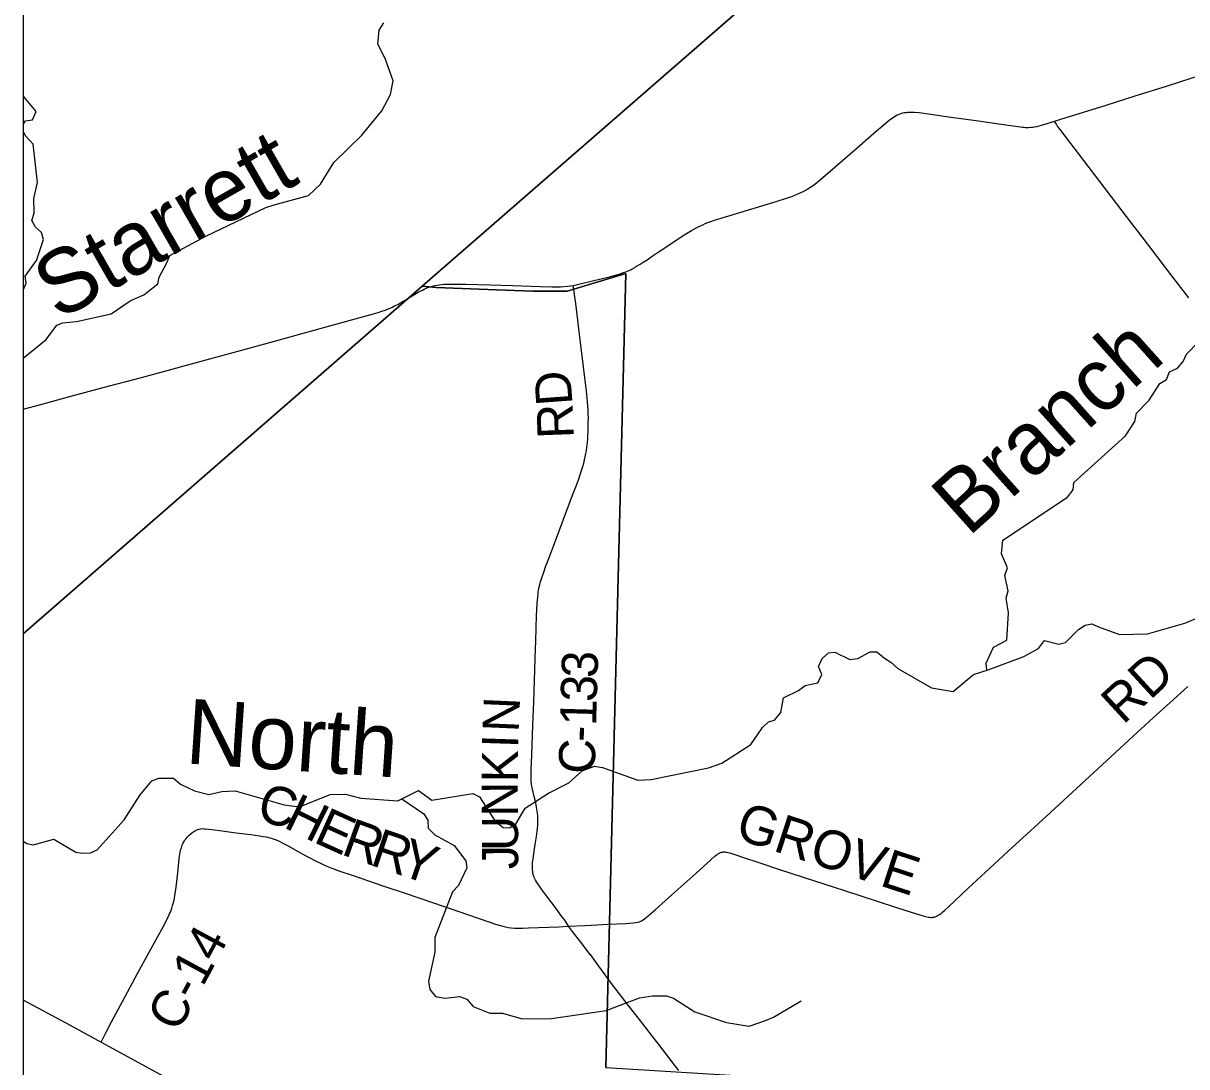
# Model space of a CAD drawing. Extents: x -13.9 to 69.1, y -25.2 to 26.1.
# Drawn here: x 1.757 to 3.383, y 18.903 to 20.361 of the extents above; entities that cross this region are included whole.
import ezdxf

# ---------------------------------------------------------------- set-up
doc = ezdxf.new("R2010")
doc.units = 0
for name, color, linetype in [('GM_X_County_Road', 7, 'Continuous'), ('GM_X_County_Road_Text', 7, 'Continuous'), ('GM_X_Minor_River', 7, 'Continuous'), ('GM_X_Minor_River_Text', 7, 'Continuous'), ('GM_X_Township', 7, 'Continuous'), ('GM_X_Township_Road', 7, 'Continuous'), ('SH_Data', 7, 'Continuous')]:
    doc.layers.add(name, color=color, linetype=linetype)

msp = doc.modelspace()

# ---------------------------------------------------------------- linework, layer by layer
at = {"layer": 'GM_X_County_Road'}
for points in [[(3.1987, 20.2246), (3.2075, 20.2273), (3.2707, 20.2469), (3.3115, 20.2598), (3.3566, 20.2741), (3.3911, 20.285), (3.4288, 20.2967), (3.4851, 20.3141), (3.5064, 20.3207), (3.5287, 20.3277), (3.5536, 20.3355), (3.5681, 20.3403), (3.5706, 20.3415), (3.5726, 20.3428), (3.577, 20.3461)], [(2.6062, 20.0171), (2.6084, 20.0182), (2.6104, 20.0194), (2.6121, 20.0205), (2.6194, 20.0248), (2.6237, 20.0275), (2.6293, 20.0311), (2.635, 20.0349), (2.6462, 20.0426), (2.6677, 20.057), (2.6796, 20.0647), (2.6911, 20.0717), (2.6994, 20.0763), (2.7027, 20.0779), (2.7069, 20.08), (2.7103, 20.0815), (2.7141, 20.083), (2.7184, 20.0845), (2.7235, 20.0863), (2.7389, 20.0911), (2.774, 20.1018), (2.8097, 20.1125), (2.824, 20.117), (2.8302, 20.1191), (2.8345, 20.1208), (2.8387, 20.1225), (2.8423, 20.124), (2.8463, 20.1259), (2.8499, 20.1278), (2.8535, 20.1298), (2.8567, 20.1319), (2.8603, 20.1344), (2.8637, 20.1368), (2.8717, 20.1433), (2.923, 20.1876), (2.9496, 20.2109), (2.9604, 20.2202), (2.9678, 20.2263), (2.9701, 20.228), (2.9724, 20.2295), (2.9744, 20.2309), (2.9766, 20.2321), (2.9789, 20.2333), (2.9806, 20.2341), (2.9828, 20.235), (2.985, 20.2357), (2.9868, 20.2361), (2.9889, 20.2366), (2.9911, 20.2369), (2.9932, 20.2372), (2.9954, 20.2373), (2.9976, 20.2374), (3.0003, 20.2374), (3.0031, 20.2373), (3.0096, 20.2367), (3.0321, 20.2334), (3.0474, 20.2313), (3.0924, 20.2251), (3.1206, 20.221), (3.1538, 20.2163), (3.1561, 20.2161), (3.1582, 20.216), (3.1622, 20.2159), (3.1655, 20.2162), (3.1683, 20.2164), (3.1709, 20.2167), (3.174, 20.2173), (3.177, 20.218), (3.1803, 20.219), (3.1884, 20.2213), (3.1987, 20.2246)], [(2.526, 19.9951), (2.5318, 19.9963), (2.5547, 20.0019), (2.573, 20.0063), (2.5816, 20.0085), (2.587, 20.01), (2.5927, 20.0118), (2.5963, 20.013), (2.5992, 20.0141), (2.6019, 20.0151), (2.605, 20.0165), (2.6062, 20.0171)], [(2.2928, 19.9756), (2.296, 19.9776), (2.309, 19.9855), (2.3121, 19.9872), (2.315, 19.9887), (2.3176, 19.99), (2.3201, 19.9911), (2.3227, 19.9922), (2.3259, 19.9933), (2.3293, 19.9943), (2.3324, 19.995), (2.3356, 19.9956), (2.3391, 19.9961), (2.3423, 19.9965), (2.345, 19.9967)], [(2.345, 19.9967), (2.3463, 19.9968), (2.3574, 19.997), (2.3756, 19.9968), (2.4093, 19.9959), (2.4414, 19.9951), (2.4795, 19.9938), (2.4961, 19.9933), (2.5021, 19.9933), (2.5079, 19.9933), (2.5128, 19.9936), (2.5175, 19.9939), (2.522, 19.9944), (2.526, 19.9951)], [(2.5195, 19.0996), (2.5164, 19.1043), (2.514, 19.1081), (2.5096, 19.1139), (2.502, 19.1243), (2.4886, 19.1424), (2.4817, 19.1517), (2.4786, 19.1559), (2.4773, 19.1578), (2.4747, 19.1617), (2.4733, 19.1641), (2.4723, 19.1661), (2.4714, 19.168), (2.4707, 19.1698), (2.47, 19.1721), (2.4695, 19.1742), (2.4692, 19.1763), (2.4689, 19.1787), (2.4688, 19.1811), (2.4688, 19.1835), (2.4688, 19.1858), (2.4691, 19.1881), (2.4698, 19.1939), (2.4719, 19.208), (2.4728, 19.2138), (2.4746, 19.225), (2.4756, 19.2324), (2.476, 19.2369), (2.4763, 19.2403), (2.4764, 19.2436), (2.4764, 19.2468), (2.4764, 19.2507), (2.4762, 19.254), (2.4759, 19.2575), (2.4756, 19.2605), (2.4752, 19.2635), (2.4747, 19.2663), (2.4741, 19.2695), (2.4735, 19.2721), (2.4714, 19.2808), (2.469, 19.2912), (2.4682, 19.2951), (2.4676, 19.2987), (2.4672, 19.3019), (2.467, 19.3047), (2.467, 19.3108), (2.4673, 19.3201), (2.4675, 19.3291), (2.4679, 19.3385), (2.4696, 19.3813), (2.4707, 19.4134), (2.4716, 19.4426), (2.4727, 19.4741), (2.4734, 19.4985), (2.4747, 19.5341), (2.4755, 19.5502), (2.4762, 19.5599), (2.4767, 19.5638), (2.477, 19.5667), (2.4775, 19.5693), (2.4779, 19.5717), (2.4784, 19.5739), (2.4791, 19.5766), (2.4798, 19.5795), (2.4807, 19.5824), (2.4825, 19.588), (2.4846, 19.5946), (2.4872, 19.6019), (2.4916, 19.6135), (2.5009, 19.6383), (2.5167, 19.6796), (2.5259, 19.7042), (2.5303, 19.716), (2.5336, 19.7248), (2.538, 19.7377), (2.5393, 19.742), (2.5406, 19.7468), (2.5417, 19.7513), (2.5426, 19.7554), (2.5435, 19.7602), (2.5442, 19.7642), (2.5449, 19.7693), (2.5456, 19.7748), (2.5461, 19.781), (2.5464, 19.7854), (2.5467, 19.7908), (2.5468, 19.7955), (2.5469, 19.8028), (2.547, 19.8104), (2.5469, 19.8153), (2.5467, 19.8199), (2.5457, 19.8336), (2.5444, 19.8472), (2.5362, 19.9156), (2.5293, 19.9698), (2.526, 19.9951)], [(1.7571, 19.8221), (1.7818, 19.8288), (1.8236, 19.8402), (1.8756, 19.8542), (1.9223, 19.8666), (2.0075, 19.8897), (2.066, 19.9054), (2.1136, 19.9186), (2.15, 19.9287), (2.226, 19.9497), (2.2469, 19.9556), (2.2534, 19.9575), (2.2585, 19.9592), (2.2617, 19.9602), (2.2651, 19.9615), (2.2686, 19.9628), (2.2724, 19.9645), (2.2762, 19.9664), (2.2805, 19.9685), (2.2883, 19.973), (2.2928, 19.9756)], [(2.5513, 19.1011), (2.5742, 19.1024), (2.5996, 19.1036), (2.6043, 19.1039), (2.6096, 19.1044), (2.6134, 19.105), (2.6165, 19.1056), (2.6181, 19.106), (2.6193, 19.1064), (2.6203, 19.1068), (2.6215, 19.1074), (2.6235, 19.1086), (2.6256, 19.11), (2.6273, 19.1114), (2.6404, 19.1226), (2.6638, 19.1436), (2.6974, 19.1736), (2.718, 19.1924), (2.7245, 19.198), (2.7264, 19.1994), (2.7282, 19.2007), (2.7294, 19.2015), (2.7306, 19.2021), (2.7317, 19.2026), (2.7327, 19.203), (2.7336, 19.2032), (2.7348, 19.2034), (2.7359, 19.2035), (2.737, 19.2036), (2.7383, 19.2035), (2.7398, 19.2033), (2.7418, 19.2029), (2.7441, 19.2023), (2.7475, 19.2013), (2.7531, 19.1995), (2.7626, 19.1963), (2.7869, 19.1881), (2.8128, 19.1797), (2.8487, 19.1678), (2.8763, 19.1589), (2.9049, 19.1497), (2.9764, 19.1266), (2.9896, 19.1223), (3.0118, 19.115), (3.0183, 19.1133), (3.0226, 19.1124), (3.024, 19.1122), (3.0257, 19.1121), (3.0271, 19.1121), (3.0282, 19.1122), (3.0292, 19.1123), (3.0304, 19.1126), (3.0316, 19.1129), (3.0327, 19.1133), (3.0339, 19.1138), (3.035, 19.1143), (3.0361, 19.115), (3.038, 19.1162), (3.04, 19.1177), (3.0425, 19.1197), (3.0454, 19.1223), (3.0505, 19.127), (3.078, 19.1528), (3.1023, 19.1754), (3.1199, 19.1916), (3.1341, 19.2048), (3.1598, 19.2283), (3.1927, 19.2583), (3.23, 19.2928), (3.2652, 19.3254), (3.3027, 19.3597), (3.3372, 19.3913), (3.36, 19.412), (3.3848, 19.4348)], [(1.8658, 18.9379), (1.8729, 18.9516), (1.8805, 18.9662), (1.899, 19.0007), (1.9174, 19.0346), (1.9274, 19.0531), (1.9355, 19.0679), (1.9525, 19.099), (1.9581, 19.1095), (1.9616, 19.1169), (1.9627, 19.1194), (1.9638, 19.1224), (1.9648, 19.1251), (1.9659, 19.1285), (1.9668, 19.1314), (1.9675, 19.1342), (1.9681, 19.1368), (1.9686, 19.1394), (1.9691, 19.1424), (1.9709, 19.1541), (1.973, 19.1742), (1.9751, 19.1945), (1.9755, 19.1975), (1.9759, 19.2005), (1.9763, 19.203), (1.9768, 19.205), (1.9774, 19.2072), (1.9781, 19.2094), (1.9787, 19.2111), (1.9794, 19.2131), (1.9803, 19.2153), (1.9814, 19.2175), (1.9824, 19.2192), (1.9835, 19.2208), (1.9848, 19.2225), (1.9861, 19.224), (1.9891, 19.227), (1.9923, 19.2298), (1.9939, 19.231), (1.9955, 19.2321), (1.997, 19.2329), (1.9986, 19.2337), (1.9998, 19.2343), (2.0015, 19.2349), (2.0032, 19.2354), (2.0055, 19.2358), (2.0076, 19.2361), (2.0095, 19.236), (2.0116, 19.2359), (2.0209, 19.2349), (2.035, 19.2331), (2.0549, 19.2304), (2.0753, 19.2277), (2.0873, 19.2261), (2.0921, 19.2253), (2.0965, 19.2245), (2.0998, 19.2239), (2.1025, 19.2233), (2.105, 19.2225), (2.1078, 19.2216), (2.1107, 19.2204), (2.114, 19.219), (2.121, 19.2154), (2.1264, 19.2125), (2.147, 19.201), (2.1568, 19.1956), (2.1658, 19.1909), (2.1734, 19.1873), (2.179, 19.1848), (2.1836, 19.1829), (2.1883, 19.1811), (2.1998, 19.1768), (2.2167, 19.171), (2.2304, 19.1663), (2.2599, 19.1563), (2.2908, 19.146), (2.3278, 19.1334), (2.3647, 19.1207), (2.4079, 19.1059), (2.4174, 19.1027), (2.4274, 19.0998), (2.4313, 19.0988), (2.4349, 19.0981), (2.4392, 19.0975), (2.4438, 19.0972), (2.4486, 19.097), (2.4548, 19.097), (2.4635, 19.0973), (2.5057, 19.0989), (2.5195, 19.0996)], [(2.5195, 19.0996), (2.5421, 19.1006), (2.5513, 19.1011)], [(1.7571, 18.9965), (1.7574, 18.9963), (1.8227, 18.9615), (1.8658, 18.9379)], [(1.8658, 18.9379), (1.8927, 18.9232), (1.9675, 18.8821), (2.0184, 18.8534), (2.1339, 18.788), (2.1583, 18.7741), (2.177, 18.7638), (2.2094, 18.7457), (2.2492, 18.7235), (2.2782, 18.7076), (2.3823, 18.6498), (2.4096, 18.6341), (2.4426, 18.6155)]]:
    msp.add_lwpolyline(points, dxfattribs=at)
at = {"layer": 'GM_X_Minor_River'}
for points in [[(1.7571, 19.8936), (1.7891, 19.9194), (1.8039, 19.9395), (1.8124, 19.943), (1.8317, 19.9449), (1.8801, 19.9554), (1.9066, 19.9738), (1.9256, 19.9819), (1.9454, 19.9972), (1.9473, 20.0066), (1.958, 20.0268), (1.9622, 20.0369), (2.0122, 20.0641), (2.0961, 20.1042), (2.1076, 20.1076), (2.1557, 20.1207), (2.1728, 20.1364), (2.1914, 20.167), (2.2304, 20.2049), (2.2582, 20.239), (2.2704, 20.2617), (2.2743, 20.2809), (2.263, 20.3123), (2.2528, 20.3321), (2.2544, 20.3517), (2.261, 20.3618)], [(1.7571, 20.2199), (1.7604, 20.2249), (1.7699, 20.2265), (1.7751, 20.2381), (1.7589, 20.2576), (1.7571, 20.2592)], [(1.7571, 19.9887), (1.7613, 19.9984), (1.7597, 20.0079), (1.7755, 20.0301), (1.7854, 20.0594), (1.7828, 20.0693), (1.7742, 20.0763), (1.7692, 20.0859), (1.7724, 20.096), (1.7717, 20.1164), (1.7768, 20.1388), (1.7711, 20.1927), (1.7605, 20.2038), (1.7571, 20.2101)], [(3.104, 19.4573), (3.1031, 19.4671), (3.1135, 19.4895), (3.1319, 19.4993), (3.1344, 19.5378), (3.1313, 19.5579), (3.1339, 19.5684), (3.1294, 19.5899), (3.133, 19.6004), (3.1245, 19.6202), (3.1264, 19.6394), (3.2167, 19.6994), (3.2249, 19.7095), (3.2257, 19.7196), (3.2979, 19.785), (3.311, 19.8048), (3.3132, 19.8168), (3.331, 19.8346), (3.3458, 19.858), (3.3553, 19.8637), (3.3595, 19.8742), (3.3704, 19.8795), (3.3786, 19.8888), (3.3832, 19.8992), (3.4003, 19.9168)], [(1.7998, 19.2212), (1.8305, 19.2032), (1.8393, 19.2016), (1.8511, 19.2025), (1.8606, 19.2067), (1.898, 19.2483), (1.9204, 19.2832), (1.9369, 19.3029), (1.9464, 19.3068), (1.967, 19.3064), (1.977, 19.2983), (1.9964, 19.2888), (2.0166, 19.2838), (2.0348, 19.2882), (2.0534, 19.289), (2.1219, 19.2693), (2.1432, 19.2664), (2.1859, 19.2836), (2.2075, 19.2843), (2.229, 19.2785), (2.2806, 19.2751), (2.3095, 19.2895), (2.3282, 19.2758), (2.3856, 19.285), (2.3947, 19.2805), (2.4168, 19.2467), (2.4278, 19.2378), (2.4372, 19.2373), (2.4461, 19.2433), (2.4589, 19.2645), (2.4912, 19.2858), (2.5198, 19.2999), (2.5382, 19.317), (2.5555, 19.3233), (2.567, 19.3217), (2.616, 19.3038), (2.6349, 19.3046), (2.7151, 19.3211), (2.7337, 19.3277), (2.7742, 19.3535), (2.7904, 19.3773), (2.799, 19.3855), (2.8074, 19.3875), (2.816, 19.3983), (2.82, 19.419), (2.8407, 19.4292), (2.85, 19.4363), (2.8679, 19.44), (2.8734, 19.4516), (2.8689, 19.4625), (2.8738, 19.4737), (2.8827, 19.4819), (2.8918, 19.4829), (2.9125, 19.4724), (2.9237, 19.474), (2.941, 19.4832), (2.9501, 19.483), (2.9611, 19.4741), (2.9698, 19.4685), (2.9795, 19.46), (3.0267, 19.4327), (3.057, 19.4275), (3.0856, 19.4514), (3.106, 19.4579), (3.1558, 19.4764), (3.1762, 19.4877), (3.1848, 19.4988), (3.2046, 19.4938), (3.2138, 19.4962), (3.2323, 19.5144), (3.2415, 19.5205), (3.2509, 19.5225), (3.26, 19.5183), (3.2895, 19.5073), (3.3287, 19.5085), (3.3808, 19.5233), (3.4008, 19.5317)], [(2.2861, 19.2779), (2.3171, 19.257), (2.3227, 19.2479), (2.3229, 19.2366), (2.3325, 19.2273), (2.3593, 19.2127), (2.3759, 19.191), (2.3771, 19.1812), (2.3656, 19.1566), (2.357, 19.1477), (2.3322, 19.0841), (2.3322, 19.0634), (2.3235, 19.0228), (2.3254, 19.0112), (2.3334, 19.0016), (2.3465, 18.9992), (2.3556, 19.0001), (2.3668, 19.0014), (2.3772, 18.998), (2.3858, 18.9876), (2.4093, 18.9782), (2.4271, 18.9782), (2.4547, 18.9705), (2.4955, 18.9706), (2.5719, 18.982), (2.6187, 18.9995), (2.6366, 19.0024), (2.6562, 19.0025), (2.6659, 18.9994), (2.696, 18.98), (2.7403, 18.9651), (2.7716, 18.9602), (2.7947, 18.9682), (2.8059, 18.9728), (2.8447, 18.9954)], [(1.7571, 19.2185), (1.7619, 19.2153), (1.771, 19.2133), (1.7998, 19.2212)]]:
    msp.add_lwpolyline(points, dxfattribs=at)
at = {"layer": 'GM_X_Township'}
for points in [[(2.668, 21.2145), (1.7571, 21.2145), (1.7571, 19.5083), (2.2857, 19.9688), (2.3149, 19.9943), (2.9282, 20.5283), (2.5207, 21.0774), (2.5376, 21.0933), (2.5713, 21.1249)], [(8.0976, 21.2145), (2.668, 21.2145), (2.5713, 21.1249), (2.5376, 21.0933), (2.5207, 21.0774), (2.9282, 20.5283), (2.3149, 19.9943), (2.3345, 19.9924), (2.4186, 19.989), (2.4692, 19.987), (2.5176, 19.987), (2.5995, 20.0118), (2.5714, 18.9023), (4.5288, 18.7816), (7.8661, 18.459), (7.9988, 20.0382), (8.0428, 20.5625)]]:
    msp.add_lwpolyline(points, close=True, dxfattribs=at)
msp.add_lwpolyline([(2.5714, 18.9023), (2.5995, 20.0118), (2.5176, 19.987), (2.4692, 19.987), (2.4186, 19.989), (2.3345, 19.9924), (2.3149, 19.9943), (2.2857, 19.9688), (1.7571, 19.5083), (1.7571, 15.7823)], dxfattribs=at)
at = {"layer": 'GM_X_Township_Road'}
for points in [[(3.3862, 19.9779), (3.3753, 19.9922), (3.3626, 20.0087), (3.3346, 20.0454), (3.3153, 20.0708), (3.3069, 20.0818), (3.2858, 20.1093), (3.2618, 20.1405), (3.232, 20.1796), (3.2064, 20.2131), (3.203, 20.2178), (3.2014, 20.2203), (3.1987, 20.2246)], [(2.5498, 19.0601), (2.5497, 19.0603), (2.5364, 19.0776), (2.525, 19.0923), (2.5195, 19.0996)], [(2.6683, 18.9045), (2.6442, 18.9362), (2.6372, 18.9451), (2.6266, 18.9591), (2.6185, 18.9692), (2.6027, 18.9893), (2.5809, 19.018), (2.5619, 19.0438), (2.5498, 19.0601)], [(2.6733, 18.898), (2.6683, 18.9045)]]:
    msp.add_lwpolyline(points, dxfattribs=at)
at = {"layer": 'SH_Data'}
msp.add_line((1.7571, 21.2145), (1.7571, 14.4145), dxfattribs=at)

# ---------------------------------------------------------------- texts
at = {"layer": 'GM_X_County_Road_Text'}
for s, height, rotation, p in [('D', 0.0506, 94.2322, (2.525, 19.8289)), ('R', 0.0506, 92.1483, (2.5268, 19.7819)), ('3', 0.0506, 87.9824, (2.5597, 19.4461)), ('RD', 0.05279, 42.5744, (3.2945, 19.3803)), ('3', 0.0506, 88.3117, (2.5587, 19.4127)), ('N', 0.0506, 87.5172, (2.4495, 19.3702)), ('1', 0.0506, 88.3794, (2.5578, 19.3792)), ('-', 0.0506, 88.3818, (2.5571, 19.3569)), ('I', 0.0506, 88.135, (2.4487, 19.348)), ('C', 0.0506, 88.3962, (2.5559, 19.3122)), ('K', 0.0505, 89.6106, (2.4484, 19.3006)), ('C', 0.0541, 344.3973, (2.0812, 19.2489)), ('N', 0.0505, 90.2472, (2.4486, 19.2529)), ('H', 0.0537, 333.8406, (2.1192, 19.2385)), ('E', 0.0538, 335.6305, (2.1611, 19.2179)), ('GROVE', 0.05407, 341.9313, (2.7502, 19.2231)), ('R', 0.054, 340.2041, (2.1999, 19.2006)), ('U', 0.0505, 90.2641, (2.4489, 19.205)), ('R', 0.054, 341.2974, (2.2402, 19.186)), ('Y', 0.054, 341.2925, (2.2798, 19.1726)), ('J', 0.0505, 90.2666, (2.449, 19.1795)), ('C-14', 0.05153, 61.631, (1.9734, 18.9499))]:
    msp.add_text(s, height=height, rotation=rotation, dxfattribs=at).set_placement(p)
at = {"layer": 'GM_X_Minor_River_Text'}
for s, height, rotation, p in [('Starrett', 0.08926, 29.8322, (1.8063, 19.9451)), ('Branch', 0.08809, 41.86, (3.078, 19.6426)), ('North', 0.09061, 356.1435, (1.9824, 19.3274))]:
    msp.add_text(s, height=height, rotation=rotation, dxfattribs=at).set_placement(p)

doc.saveas('drawing.dxf')
